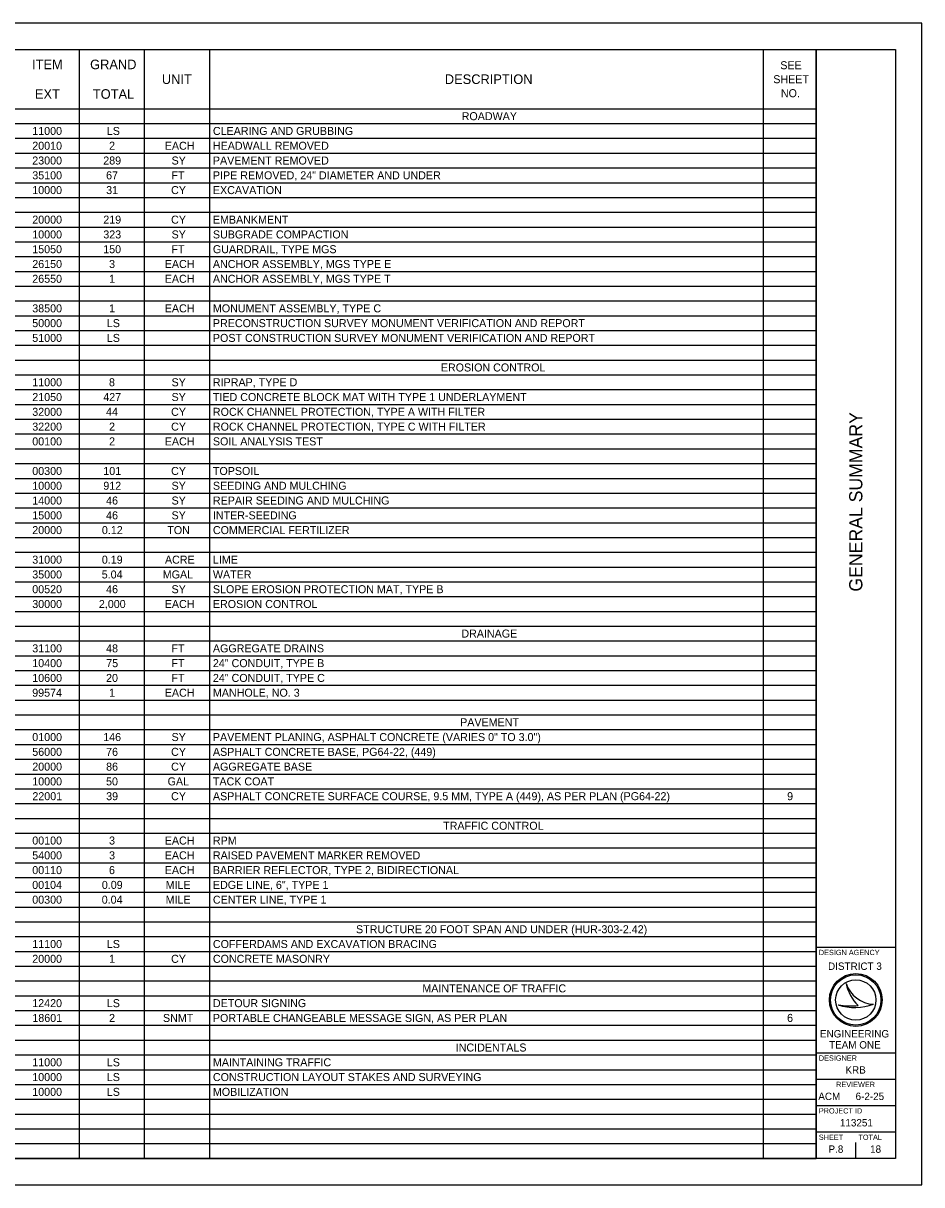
# Model space of a CAD drawing. Extents: x 0 to 34, y 0 to 22.
# Drawn here: x 16.98 to 34, y 0 to 22 of the extents above; entities that cross this region are included whole.
import ezdxf

# ---------------------------------------------------------------- set-up
doc = ezdxf.new("R2010")
doc.units = 0
for name, color, linetype in [('Default', 7, 'Continuous'), ('SH_Border', 7, 'Continuous'), ('SH_Cut_Line', 7, 'Continuous'), ('SH_Data', 7, 'Continuous')]:
    doc.layers.add(name, color=color, linetype=linetype)

msp = doc.modelspace()

# ---------------------------------------------------------------- linework, layer by layer
at = {"layer": 'Default'}
for p, q in [((1.5, 21.5), (32, 21.5)), ((18.035, 21.5), (18.035, 0.5)), ((19.27, 21.5), (19.27, 0.5)), ((20.505, 21.5), (20.505, 0.5)), ((30.995, 21.5), (30.995, 0.5)), ((32, 21.5), (32, 0.5)), ((1.5, 20.38), (32, 20.38)), ((1.5, 20.1), (32, 20.1)), ((1.5, 19.82), (32, 19.82)), ((1.5, 19.54), (32, 19.54)), ((1.5, 19.26), (32, 19.26)), ((1.5, 18.98), (32, 18.98)), ((1.5, 18.7), (32, 18.7)), ((1.5, 18.42), (32, 18.42)), ((1.5, 18.14), (32, 18.14)), ((1.5, 17.86), (32, 17.86)), ((1.5, 17.58), (32, 17.58)), ((1.5, 17.3), (32, 17.3)), ((1.5, 17.02), (32, 17.02)), ((1.5, 16.74), (32, 16.74)), ((1.5, 16.46), (32, 16.46)), ((1.5, 16.18), (32, 16.18)), ((1.5, 15.9), (32, 15.9)), ((1.5, 15.62), (32, 15.62)), ((1.5, 15.34), (32, 15.34)), ((1.5, 15.06), (32, 15.06)), ((1.5, 14.78), (32, 14.78)), ((1.5, 14.5), (32, 14.5)), ((1.5, 14.22), (32, 14.22)), ((1.5, 13.94), (32, 13.94)), ((1.5, 13.66), (32, 13.66)), ((1.5, 13.38), (32, 13.38)), ((1.5, 13.1), (32, 13.1)), ((1.5, 12.82), (32, 12.82)), ((1.5, 12.54), (32, 12.54)), ((1.5, 12.26), (32, 12.26)), ((1.5, 11.98), (32, 11.98)), ((1.5, 11.7), (32, 11.7)), ((1.5, 11.42), (32, 11.42)), ((1.5, 11.14), (32, 11.14)), ((1.5, 10.86), (32, 10.86)), ((1.5, 10.58), (32, 10.58)), ((1.5, 10.3), (32, 10.3)), ((1.5, 10.02), (32, 10.02)), ((1.5, 9.74), (32, 9.74)), ((1.5, 9.46), (32, 9.46)), ((1.5, 9.18), (32, 9.18)), ((1.5, 8.9), (32, 8.9)), ((1.5, 8.62), (32, 8.62)), ((1.5, 8.34), (32, 8.34)), ((1.5, 8.06), (32, 8.06)), ((1.5, 7.78), (32, 7.78)), ((1.5, 7.5), (32, 7.5)), ((1.5, 7.22), (32, 7.22)), ((1.5, 6.94), (32, 6.94)), ((1.5, 6.66), (32, 6.66)), ((1.5, 6.38), (32, 6.38)), ((1.5, 6.1), (32, 6.1)), ((1.5, 5.82), (32, 5.82)), ((1.5, 5.54), (32, 5.54)), ((1.5, 5.26), (32, 5.26)), ((1.5, 4.98), (32, 4.98)), ((1.5, 4.7), (32, 4.7)), ((1.5, 4.42), (32, 4.42)), ((1.5, 4.14), (32, 4.14)), ((1.5, 3.86), (32, 3.86)), ((1.5, 3.58), (32, 3.58)), ((1.5, 3.3), (32, 3.3)), ((1.5, 3.02), (32, 3.02)), ((1.5, 2.74), (32, 2.74)), ((1.5, 2.46), (32, 2.46)), ((1.5, 2.18), (32, 2.18)), ((1.5, 1.9), (32, 1.9)), ((1.5, 1.62), (32, 1.62)), ((1.5, 1.34), (32, 1.34)), ((1.5, 1.06), (32, 1.06)), ((1.5, 0.78), (32, 0.78)), ((1.5, 0.5), (32, 0.5))]:
    msp.add_line(p, q, dxfattribs=at)
at = {"layer": 'SH_Border'}
for p, q in [((32, 0.5), (32, 21.5)), ((32, 4.5), (33.5, 4.5)), ((32, 2.5), (33.5, 2.5)), ((32, 2), (33.5, 2)), ((32, 1.5), (33.5, 1.5)), ((32, 1), (33.5, 1))]:
    msp.add_line(p, q, dxfattribs=at)
msp.add_lwpolyline([(1.5, 21.5), (33.5, 21.5), (33.5, 0.5), (1.5, 0.5)], close=True, dxfattribs=at)
at = {"layer": 'SH_Cut_Line'}
msp.add_lwpolyline([(0, 0), (34, 0), (34, 22), (0, 22)], close=True, dxfattribs=at)
at = {"layer": 'SH_Data'}
for p, q in [((32.567, 3.81), (32.567, 3.81)), ((32.417, 3.41), (32.417, 3.41)), ((32.75, 3.5), (32.75, 3.5)), ((33.087, 3.419), (33.087, 3.419)), ((32.375, 0.675), (32.375, 0.675)), ((32.75, 0.5), (32.75, 0.8))]:
    msp.add_line(p, q, dxfattribs=at)
for radius in [0.5, 0.477, 0.477, 0.382]:
    msp.add_circle((32.75, 3.5), radius, dxfattribs=at)
for centre, radius, start, end in [((33.116, 3.998), 0.58, 198.9257, 198.9319), ((33.347, 3.97), 0.796, 191.6379, 191.6421), ((33.116, 3.998), 0.58, 198.9319, 267.1657), ((33.347, 3.97), 0.796, 191.6421, 226.0947), ((32.739, 4.37), 1.013, 251.4576, 290.0832), ((32.648, 4.654), 1.266, 259.4964, 259.4995), ((32.739, 4.37), 1.013, 251.4527, 251.4576), ((32.648, 4.654), 1.266, 259.4995, 276.6672)]:
    msp.add_arc(centre, radius, start, end, dxfattribs=at)

# ---------------------------------------------------------------- texts
at = {"layer": 'Default'}
for s, height, p in [('ITEM', 0.1818, (17.145, 21.129)), ('GRAND', 0.1818, (18.245, 21.129)), ('SEE ', 0.1515, (31.32, 21.129)), ('UNIT', 0.1818, (19.604, 20.849)), ('DESCRIPTION', 0.18184, (24.965, 20.849)), ('SHEET ', 0.1515, (31.187, 20.864)), ('EXT', 0.1818, (17.199, 20.569)), ('TOTAL', 0.1818, (18.297, 20.569)), ('NO.', 0.1515, (31.331, 20.599)), ('ROADWAY', 0.1515, (25.284, 20.164)), ('11000', 0.1515, (17.149, 19.884)), ('LS', 0.1515, (18.562, 19.884)), ('CLEARING AND GRUBBING', 0.15153, (20.571, 19.884)), ('20010', 0.1515, (17.149, 19.604)), ('2', 0.152, (18.604, 19.604)), ('EACH', 0.1515, (19.659, 19.604)), ('HEADWALL REMOVED', 0.15153, (20.571, 19.604)), ('23000', 0.1515, (17.149, 19.324)), ('289', 0.1515, (18.494, 19.324)), ('SY', 0.1515, (19.788, 19.324)), ('PAVEMENT REMOVED', 0.15153, (20.571, 19.324)), ('35100', 0.1515, (17.149, 19.044)), ('67', 0.1515, (18.548, 19.044)), ('FT', 0.1515, (19.786, 19.044)), ('PIPE REMOVED, 24" DIAMETER AND UNDER', 0.15153, (20.571, 19.044)), ('10000', 0.1515, (17.149, 18.764)), ('31', 0.1515, (18.549, 18.764)), ('CY', 0.1515, (19.779, 18.764)), ('EXCAVATION', 0.1515, (20.571, 18.764)), ('20000', 0.1515, (17.149, 18.204)), ('219', 0.1515, (18.494, 18.204)), ('CY', 0.1515, (19.779, 18.204)), ('EMBANKMENT', 0.1515, (20.571, 18.204)), ('10000', 0.1515, (17.149, 17.924)), ('323', 0.1515, (18.495, 17.924)), ('SY', 0.1515, (19.788, 17.924)), ('SUBGRADE COMPACTION', 0.15153, (20.571, 17.924)), ('15050', 0.1515, (17.149, 17.644)), ('150', 0.1515, (18.493, 17.644)), ('FT', 0.1515, (19.786, 17.644)), ('GUARDRAIL, TYPE MGS', 0.15153, (20.571, 17.644)), ('26150', 0.1515, (17.149, 17.364)), ('3', 0.152, (18.604, 17.364)), ('EACH', 0.1515, (19.659, 17.364)), ('ANCHOR ASSEMBLY, MGS TYPE E', 0.15153, (20.571, 17.364)), ('26550', 0.1515, (17.149, 17.084)), ('1', 0.152, (18.604, 17.084)), ('EACH', 0.1515, (19.659, 17.084)), ('ANCHOR ASSEMBLY, MGS TYPE T', 0.15153, (20.571, 17.084)), ('38500', 0.1515, (17.149, 16.524)), ('1', 0.152, (18.604, 16.524)), ('EACH', 0.1515, (19.659, 16.524)), ('MONUMENT ASSEMBLY, TYPE C', 0.15153, (20.571, 16.524)), ('50000', 0.1515, (17.149, 16.244)), ('LS', 0.1515, (18.562, 16.244)), ('PRECONSTRUCTION SURVEY MONUMENT VERIFICATION AND REPORT', 0.15153, (20.571, 16.244)), ('51000', 0.1515, (17.149, 15.964)), ('LS', 0.1515, (18.562, 15.964)), ('POST CONSTRUCTION SURVEY MONUMENT VERIFICATION AND REPORT', 0.15153, (20.571, 15.964)), ('EROSION CONTROL', 0.15153, (24.889, 15.404)), ('11000', 0.1515, (17.149, 15.124)), ('8', 0.152, (18.602, 15.124)), ('SY', 0.1515, (19.788, 15.124)), ('RIPRAP, TYPE D', 0.15153, (20.571, 15.124)), ('21050', 0.1515, (17.149, 14.844)), ('427', 0.1515, (18.494, 14.844)), ('SY', 0.1515, (19.788, 14.844)), ('TIED CONCRETE BLOCK MAT WITH TYPE 1 UNDERLAYMENT', 0.15153, (20.571, 14.844)), ('32000', 0.1515, (17.149, 14.564)), ('44', 0.1515, (18.546, 14.564)), ('CY', 0.1515, (19.779, 14.564)), ('ROCK CHANNEL PROTECTION, TYPE A WITH FILTER', 0.15153, (20.571, 14.564)), ('32200', 0.1515, (17.149, 14.284)), ('2', 0.152, (18.604, 14.284)), ('CY', 0.1515, (19.779, 14.284)), ('ROCK CHANNEL PROTECTION, TYPE C WITH FILTER', 0.15153, (20.571, 14.284)), ('00100', 0.1515, (17.149, 14.004)), ('2', 0.152, (18.604, 14.004)), ('EACH', 0.1515, (19.659, 14.004)), ('SOIL ANALYSIS TEST', 0.15153, (20.571, 14.004)), ('00300', 0.1515, (17.149, 13.444)), ('101', 0.1515, (18.495, 13.444)), ('CY', 0.1515, (19.779, 13.444)), ('TOPSOIL', 0.1515, (20.571, 13.444)), ('10000', 0.1515, (17.149, 13.164)), ('912', 0.1515, (18.495, 13.164)), ('SY', 0.1515, (19.788, 13.164)), ('SEEDING AND MULCHING', 0.15153, (20.571, 13.164)), ('14000', 0.1515, (17.149, 12.884)), ('46', 0.1515, (18.548, 12.884)), ('SY', 0.1515, (19.788, 12.884)), ('REPAIR SEEDING AND MULCHING', 0.15153, (20.571, 12.884)), ('15000', 0.1515, (17.149, 12.604)), ('46', 0.1515, (18.548, 12.604)), ('SY', 0.1515, (19.788, 12.604)), ('INTER-SEEDING', 0.15153, (20.571, 12.604)), ('20000', 0.1515, (17.149, 12.324)), ('0.12', 0.1515, (18.468, 12.324)), ('TON', 0.1515, (19.707, 12.324)), ('COMMERCIAL FERTILIZER', 0.15153, (20.571, 12.324)), ('31000', 0.1515, (17.149, 11.764)), ('0.19', 0.1515, (18.467, 11.764)), ('ACRE', 0.1515, (19.663, 11.764)), ('LIME', 0.1515, (20.571, 11.764)), ('35000', 0.1515, (17.149, 11.484)), ('5.04', 0.1515, (18.465, 11.484)), ('MGAL', 0.1515, (19.621, 11.484)), ('WATER', 0.1515, (20.571, 11.484)), ('00520', 0.1515, (17.149, 11.204)), ('46', 0.1515, (18.548, 11.204)), ('SY', 0.1515, (19.788, 11.204)), ('SLOPE EROSION PROTECTION MAT, TYPE B', 0.15153, (20.571, 11.204)), ('30000', 0.1515, (17.149, 10.924)), ('2,000', 0.1515, (18.411, 10.924)), ('EACH', 0.1515, (19.659, 10.924)), ('EROSION CONTROL', 0.15153, (20.571, 10.924)), ('DRAINAGE', 0.1515, (25.278, 10.364)), ('31100', 0.1515, (17.149, 10.084)), ('48', 0.1515, (18.548, 10.084)), ('FT', 0.1515, (19.786, 10.084)), ('AGGREGATE DRAINS', 0.15153, (20.571, 10.084)), ('10400', 0.1515, (17.149, 9.804)), ('75', 0.1515, (18.55, 9.804)), ('FT', 0.1515, (19.786, 9.804)), ('24" CONDUIT, TYPE B', 0.15153, (20.571, 9.804)), ('10600', 0.1515, (17.149, 9.524)), ('20', 0.1515, (18.547, 9.524)), ('FT', 0.1515, (19.786, 9.524)), ('24" CONDUIT, TYPE C', 0.15153, (20.571, 9.524)), ('99574', 0.1515, (17.148, 9.244)), ('1', 0.152, (18.604, 9.244)), ('EACH', 0.1515, (19.659, 9.244)), ('MANHOLE, NO. 3', 0.15153, (20.571, 9.244)), ('PAVEMENT', 0.1515, (25.255, 8.684)), ('01000', 0.1515, (17.149, 8.404)), ('146', 0.1515, (18.493, 8.404)), ('SY', 0.1515, (19.788, 8.404)), ('PAVEMENT PLANING, ASPHALT CONCRETE (VARIES 0" TO 3.0")', 0.15153, (20.571, 8.404)), ('56000', 0.1515, (17.149, 8.124)), ('76', 0.1515, (18.548, 8.124)), ('CY', 0.1515, (19.779, 8.124)), ('ASPHALT CONCRETE BASE, PG64-22, (449)', 0.15153, (20.571, 8.124)), ('20000', 0.1515, (17.149, 7.844)), ('86', 0.1515, (18.548, 7.844)), ('CY', 0.1515, (19.779, 7.844)), ('AGGREGATE BASE', 0.15153, (20.571, 7.844)), ('10000', 0.1515, (17.149, 7.564)), ('50', 0.1515, (18.547, 7.564)), ('GAL', 0.1515, (19.713, 7.564)), ('TACK COAT', 0.1515, (20.571, 7.564)), ('22001', 0.1515, (17.151, 7.284)), ('39', 0.1515, (18.549, 7.284)), ('CY', 0.1515, (19.779, 7.284)), ('ASPHALT CONCRETE SURFACE COURSE, 9.5 MM, TYPE A (449), AS PER PLAN (PG64-22)', 0.15153, (20.571, 7.284)), ('9', 0.152, (31.449, 7.284)), ('TRAFFIC CONTROL', 0.15153, (24.933, 6.724)), ('00100', 0.1515, (17.149, 6.444)), ('3', 0.152, (18.604, 6.444)), ('EACH', 0.1515, (19.659, 6.444)), ('RPM', 0.1515, (20.571, 6.444)), ('54000', 0.1515, (17.149, 6.164)), ('3', 0.152, (18.604, 6.164)), ('EACH', 0.1515, (19.659, 6.164)), ('RAISED PAVEMENT MARKER REMOVED', 0.15153, (20.571, 6.164)), ('00110', 0.1515, (17.149, 5.884)), ('6', 0.152, (18.602, 5.884)), ('EACH', 0.1515, (19.659, 5.884)), ('BARRIER REFLECTOR, TYPE 2, BIDIRECTIONAL', 0.15153, (20.571, 5.884)), ('00104', 0.1515, (17.148, 5.604)), ('0.09', 0.1515, (18.467, 5.604)), ('MILE', 0.1515, (19.676, 5.604)), ('EDGE LINE, 6", TYPE 1', 0.15153, (20.571, 5.604)), ('00300', 0.1515, (17.149, 5.324)), ('0.04', 0.1515, (18.465, 5.324)), ('MILE', 0.1515, (19.676, 5.324)), ('CENTER LINE, TYPE 1', 0.15153, (20.571, 5.324)), ('STRUCTURE 20 FOOT SPAN AND UNDER (HUR-303-2.42)', 0.15153, (23.282, 4.764)), ('11100', 0.1515, (17.149, 4.484)), ('LS', 0.1515, (18.562, 4.484)), ('COFFERDAMS AND EXCAVATION BRACING', 0.15153, (20.571, 4.484)), ('20000', 0.1515, (17.149, 4.204)), ('1', 0.152, (18.604, 4.204)), ('CY', 0.1515, (19.779, 4.204)), ('CONCRETE MASONRY', 0.15153, (20.571, 4.204)), ('MAINTENANCE OF TRAFFIC', 0.15153, (24.539, 3.644)), ('12420', 0.1515, (17.149, 3.364)), ('LS', 0.1515, (18.562, 3.364)), ('DETOUR SIGNING', 0.15153, (20.571, 3.364)), ('18601', 0.1515, (17.151, 3.084)), ('2', 0.152, (18.604, 3.084)), ('SNMT', 0.1515, (19.625, 3.084)), ('PORTABLE CHANGEABLE MESSAGE SIGN, AS PER PLAN', 0.15153, (20.571, 3.084)), ('6', 0.152, (31.448, 3.084)), ('INCIDENTALS', 0.15153, (25.171, 2.524)), ('11000', 0.1515, (17.149, 2.244)), ('LS', 0.1515, (18.562, 2.244)), ('MAINTAINING TRAFFIC', 0.15153, (20.571, 2.244)), ('10000', 0.1515, (17.149, 1.964)), ('LS', 0.1515, (18.562, 1.964)), ('CONSTRUCTION LAYOUT STAKES AND SURVEYING', 0.15153, (20.571, 1.964)), ('10000', 0.1515, (17.149, 1.684)), ('LS', 0.1515, (18.562, 1.684)), ('MOBILIZATION', 0.15153, (20.571, 1.684))]:
    msp.add_text(s, height=height, dxfattribs=at).set_placement(p)
at = {"layer": 'SH_Data'}
msp.add_text('GENERAL SUMMARY', height=0.25, rotation=90, dxfattribs=at).set_placement((32.875, 11.235))
for s, height, p in [('DESIGN AGENCY', 0.1, (32.05, 4.35)), ('DISTRICT 3', 0.14, (32.224, 4.07)), ('ENGINEERING', 0.14, (32.071, 2.79)), ('TEAM ONE', 0.14, (32.244, 2.58)), ('DESIGNER', 0.1, (32.05, 2.35)), ('KRB', 0.14, (32.554, 2.105)), ('REVIEWER', 0.1, (32.378, 1.85)), ('ACM', 0.14, (32.04, 1.605)), ('6-2-25', 0.14, (32.746, 1.605)), ('PROJECT ID', 0.1, (32.05, 1.35)), ('113251', 0.14, (32.449, 1.105)), ('SHEET', 0.1, (32.05, 0.85)), ('TOTAL', 0.1, (32.8, 0.85)), ('P.8', 0.14, (32.233, 0.605)), ('18', 0.14, (33.021, 0.605))]:
    msp.add_text(s, height=height, dxfattribs=at).set_placement(p)

doc.saveas('drawing.dxf')
